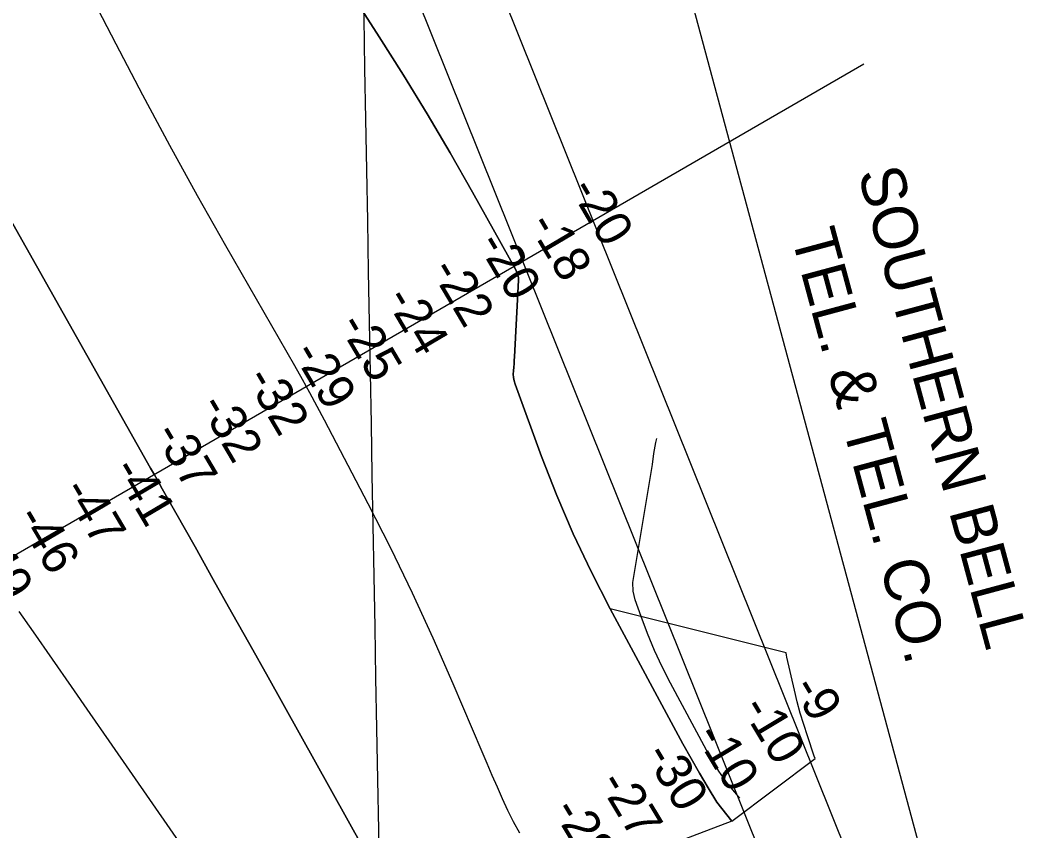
# Model space of a CAD drawing. Extents: x 3914892 to 3953151, y 242587 to 268572.
# Drawn here: x 3939590 to 3941476, y 257865 to 259377 of the extents above; entities that cross this region are included whole.
import ezdxf

# ---------------------------------------------------------------- set-up
doc = ezdxf.new("R2010")
doc.units = 0
for name, color, linetype in [('V-GRID-MAJR', 7, 'Continuous'), ('V-RIVR-RANG', 7, 'Continuous'), ('V-TOPO-DPTH', 7, 'Continuous'), ('V-TOPO-MAJR', 7, 'Continuous'), ('V-TOPO-MINR', 7, 'Continuous'), ('V-UTIL-IDEN', 7, 'Continuous'), ('V-UTIL-LINE', 7, 'Continuous')]:
    doc.layers.add(name, color=color, linetype=linetype)

msp = doc.modelspace()

# ---------------------------------------------------------------- linework, layer by layer
at = {"layer": 'V-GRID-MAJR'}
msp.add_spline([(3940428.975, 248401.018), (3940319.725, 254457.832), (3940210.42, 260517.73), (3940101.115, 266577.62), (3940101.059, 266580.712)], degree=3, dxfattribs=at)
at = {"layer": 'V-TOPO-DPTH'}
msp.add_line((3940916.7946737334, 257883.60607081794), (3940592.1881537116, 257760.18646806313), dxfattribs=at)
for points in [[(3940045.042517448, 259679.64535009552), (3940259.416958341, 259346.02710651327), (3940304.4262905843, 259274.52676481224), (3940348.5364647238, 259202.48730646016), (3940391.297901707, 259129.63917313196), (3940433.1601805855, 259056.25192315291), (3940513.3725932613, 258912.54215419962), (3940515.295097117, 258908.56889559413), (3940516.0658002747, 258906.50344468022), (3940516.741229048, 258904.39858296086), (3940518.725091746, 258897.37706114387), (3940518.887253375, 258896.70905295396), (3940519.1494097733, 258893.289819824), (3940519.103615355, 258891.91121463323), (3940511.435853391, 258748.9816995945), (3940511.044543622, 258742.54425098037), (3940510.5922374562, 258736.11152761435), (3940510.0484366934, 258729.68589212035), (3940509.4436395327, 258723.26498187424), (3940509.236969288, 258716.9035478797), (3940509.597414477, 258710.61357017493), (3940510.808532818, 258704.4307769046), (3940512.5867665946, 258698.31943992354), (3940562.0141765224, 258563.6274434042), (3940590.4767664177, 258490.91323125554), (3940620.966441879, 258419.11141004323), (3940654.4967456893, 258348.67817523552), (3940690.0541350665, 258279.15733136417), (3940825.535124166, 258027.68460056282), (3940840.7424244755, 258000.0505592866), (3940856.274320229, 257972.6040456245), (3940872.293109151, 257945.43882338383), (3940888.6364935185, 257918.46112875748), (3940916.7946737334, 257883.60607081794)], [(3940521.2747341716, 257861.190364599), (3940509.655623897, 257881.96401162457), (3940499.0032929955, 257903.2495931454), (3940488.9954816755, 257924.87646432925), (3940479.501421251, 257946.7725954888), (3940470.044684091, 257968.68477791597), (3940460.643931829, 257990.62103724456), (3940451.2805028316, 258012.57334784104), (3940397.336112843, 258139.4933336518), (3940360.0272818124, 258224.44432548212), (3940321.3852736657, 258308.76501382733), (3940280.743499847, 258392.1402469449), (3940238.7685489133, 258474.88517657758), (3940157.15210671, 258631.12796396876), (3940143.6413121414, 258656.62519658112), (3940129.9317093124, 258682.0135558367), (3940115.923894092, 258707.23860505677), (3940101.7172706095, 258732.3547809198), (3939973.24557912, 258956.39167766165), (3939920.6512738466, 259049.5280964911), (3939868.8835262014, 259143.11463003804), (3939818.355614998, 259237.3763356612), (3939768.654261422, 259332.08815600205), (3939692.0899913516, 259480.36083535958)], [(3940521.2747341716, 257861.190364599), (3940509.655623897, 257881.96401162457), (3940499.0032929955, 257903.2495931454), (3940488.9954816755, 257924.87646432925), (3940479.501421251, 257946.7725954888), (3940470.044684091, 257968.68477791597), (3940460.643931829, 257990.62103724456), (3940451.2805028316, 258012.57334784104), (3940397.336112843, 258139.4933336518), (3940360.0272818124, 258224.44432548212), (3940321.3852736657, 258308.76501382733), (3940280.743499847, 258392.1402469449), (3940238.7685489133, 258474.88517657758), (3940157.15210671, 258631.12796396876), (3940143.6413121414, 258656.62519658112), (3940129.9317093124, 258682.0135558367), (3940115.923894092, 258707.23860505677), (3940101.7172706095, 258732.3547809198), (3939973.24557912, 258956.39167766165), (3939920.6512738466, 259049.5280964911), (3939868.8835262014, 259143.11463003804), (3939818.355614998, 259237.3763356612), (3939768.654261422, 259332.08815600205), (3939692.0899913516, 259480.36083535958)], [(3939481.8310250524, 259163.69193205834), (3939832.9714719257, 258541.88976801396), (3939840.2523454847, 258528.98952955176), (3939847.5290996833, 258516.08696916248), (3939854.7996748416, 258503.18092588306), (3939862.0661306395, 258490.27256067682), (3939915.828914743, 258394.71311202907), (3939949.938412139, 258334.00353257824), (3939984.0008951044, 258273.26762191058), (3940017.992856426, 258212.49221441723), (3940051.937803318, 258151.6904757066), (3940316.8800802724, 257676.48161290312)], [(3940316.8800802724, 257676.48161290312), (3940051.937803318, 258151.6904757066), (3940017.992856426, 258212.49221441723), (3939984.0008951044, 258273.26762191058), (3939949.938412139, 258334.00353257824), (3939915.828914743, 258394.71311202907), (3939862.0661306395, 258490.27256067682), (3939854.7996748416, 258503.18092588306), (3939847.5290996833, 258516.08696916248), (3939840.2523454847, 258528.98952955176), (3939832.9714719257, 258541.88976801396), (3939481.8310250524, 259163.69193205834)], [(3940916.7946737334, 257883.60607081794), (3941071.9874333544, 258000.2995589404), (3941070.4826231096, 258004.7867699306), (3941057.63869986, 258042.28013250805), (3941050.7773749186, 258063.36526431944), (3941044.3543190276, 258084.57576696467), (3941038.588666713, 258105.9743258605), (3941033.261283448, 258127.49825558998), (3941019.018173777, 258189.10541415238), (3941018.3900835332, 258193.0934200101), (3941018.136960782, 258197.078780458), (3940690.0541350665, 258279.15733136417)], [(3940690.0541350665, 258279.15733136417), (3940825.535124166, 258027.68460056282), (3940840.7424244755, 258000.0505592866), (3940856.274320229, 257972.6040456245), (3940872.293109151, 257945.43882338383), (3940888.6364935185, 257918.46112875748), (3940916.7946737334, 257883.60607081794)]]:
    msp.add_lwpolyline(points, dxfattribs=at)
at = {"layer": 'V-TOPO-MAJR'}
msp.add_lwpolyline([(3940070.0098628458, 257579.46278085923), (3939755.701372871, 258033.1211966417), (3939720.4785539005, 258083.90690546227), (3939685.2225123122, 258134.6695160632), (3939649.9166367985, 258185.3974793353), (3939614.577538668, 258236.10234438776), (3939588.0782612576, 258274.08398232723)], dxfattribs=at)
at = {"layer": 'V-TOPO-MINR'}
for points in [[(3940916.7946737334, 257883.60607081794), (3940888.6364935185, 257918.46112875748), (3940872.293109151, 257945.43882338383), (3940856.274320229, 257972.6040456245), (3940840.7424244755, 258000.0505592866), (3940825.535124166, 258027.68460056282), (3940690.0541350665, 258279.15733136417), (3940654.4967456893, 258348.67817523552), (3940620.966441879, 258419.11141004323), (3940590.4767664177, 258490.91323125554), (3940562.0141765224, 258563.6274434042), (3940512.5867665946, 258698.31943992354), (3940510.808532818, 258704.4307769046), (3940509.597414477, 258710.61357017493), (3940509.236969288, 258716.9035478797), (3940509.4436395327, 258723.26498187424), (3940510.0484366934, 258729.68589212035), (3940510.5922374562, 258736.11152761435), (3940511.044543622, 258742.54425098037), (3940511.435853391, 258748.9816995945), (3940519.103615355, 258891.91121463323), (3940519.1494097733, 258893.289819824), (3940518.887253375, 258896.70905295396), (3940518.725091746, 258897.37706114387), (3940516.741229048, 258904.39858296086), (3940516.0658002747, 258906.50344468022), (3940515.295097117, 258908.56889559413), (3940513.3725932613, 258912.54215419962), (3940433.1601805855, 259056.25192315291), (3940391.297901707, 259129.63917313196), (3940348.5364647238, 259202.48730646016), (3940304.4262905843, 259274.52676481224), (3940259.416958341, 259346.02710651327), (3940045.042517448, 259679.64535009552)], [(3940521.2747341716, 257861.190364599), (3940509.655623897, 257881.96401162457), (3940499.0032929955, 257903.2495931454), (3940488.9954816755, 257924.87646432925), (3940479.501421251, 257946.7725954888), (3940470.044684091, 257968.68477791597), (3940460.643931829, 257990.62103724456), (3940451.2805028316, 258012.57334784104), (3940397.336112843, 258139.4933336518), (3940360.0272818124, 258224.44432548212), (3940321.3852736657, 258308.76501382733), (3940280.743499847, 258392.1402469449), (3940238.7685489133, 258474.88517657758), (3940157.15210671, 258631.12796396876), (3940143.6413121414, 258656.62519658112), (3940129.9317093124, 258682.0135558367), (3940115.923894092, 258707.23860505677), (3940101.7172706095, 258732.3547809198), (3939973.24557912, 258956.39167766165), (3939920.6512738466, 259049.5280964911), (3939868.8835262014, 259143.11463003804), (3939818.355614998, 259237.3763356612), (3939768.654261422, 259332.08815600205), (3939692.0899913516, 259480.36083535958)], [(3940316.8800802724, 257676.48161290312), (3940051.937803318, 258151.6904757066), (3940017.992856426, 258212.49221441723), (3939984.0008951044, 258273.26762191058), (3939949.938412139, 258334.00353257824), (3939915.828914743, 258394.71311202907), (3939862.0661306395, 258490.27256067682), (3939854.7996748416, 258503.18092588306), (3939847.5290996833, 258516.08696916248), (3939840.2523454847, 258528.98952955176), (3939832.9714719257, 258541.88976801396), (3939481.8310250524, 259163.69193205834)], [(3940931.7621347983, 257926.34766184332), (3940922.088612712, 257937.50243969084), (3940908.4096784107, 257953.3660199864), (3940900.8666048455, 257964.33974285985), (3940892.5693273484, 257976.8401308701), (3940884.5486042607, 257989.50938576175), (3940876.942712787, 258002.4319409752), (3940869.613375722, 258015.52336307), (3940802.072049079, 258140.88985305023), (3940786.695478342, 258171.13178190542), (3940772.3011314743, 258201.80646002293), (3940759.380120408, 258233.13026203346), (3940747.441333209, 258264.88681330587), (3940736.4781410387, 258296.2961578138), (3940733.0126962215, 258312.51668829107), (3940732.163604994, 258328.5540451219), (3940768.8571837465, 258548.72593687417), (3940771.505786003, 258569.20815368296), (3940775.1159646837, 258589.60018195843), (3940776.6397154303, 258596.73632916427)], [(3941071.9874333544, 258000.2995589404), (3941070.4826231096, 258004.7867699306), (3941057.63869986, 258042.28013250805), (3941050.7773749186, 258063.36526431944), (3941044.3543190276, 258084.57576696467), (3941038.588666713, 258105.9743258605), (3941033.261283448, 258127.49825558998), (3941019.018173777, 258189.10541415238), (3941018.3900835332, 258193.0934200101), (3941018.136960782, 258197.078780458)]]:
    msp.add_lwpolyline(points, dxfattribs=at)
at = {"layer": 'V-UTIL-LINE'}
for p, q in [((3941072.986, 257567.442), (3939526.299, 261421.028)), ((3941262.278, 257498.559), (3939715.592, 261352.14800000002)), ((3941339.742, 257565.166), (3940398.835, 261058.278))]:
    msp.add_line(p, q, dxfattribs=at)
msp.add_lwpolyline([(3941163.0146340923, 259295.05838473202), (3936055.712848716, 256340.1292946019)], dxfattribs=at)

# ---------------------------------------------------------------- texts
at = {"layer": 'V-RIVR-RANG'}
for s, height, rotation, p in [('-20', 67.0000000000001, 300.30832571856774, (3940613.6761542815, 259061.91486141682)), ('-18', 67.00000000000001, 300.58983333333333, (3940535.927216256, 258996.13250640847)), ('-20', 67.00000000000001, 300.58983333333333, (3940440.99297931, 258960.2160530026)), ('-22', 67.00000000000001, 300.58983333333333, (3940353.8453384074, 258911.12954263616)), ('-24', 67.00000000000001, 300.58983333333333, (3940269.112916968, 258857.9557732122)), ('-25', 67.00000000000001, 300.58983333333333, (3940181.964276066, 258808.86926284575)), ('-29', 67.00000000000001, 300.58983333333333, (3940096.6949169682, 258756.6037732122)), ('-32', 67.00000000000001, 300.58983333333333, (3940008.7418695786, 258708.87968253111)), ('-32', 67.00000000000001, 300.58983333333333, (3939922.5328695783, 258658.20468253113)), ('-37', 67.00000000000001, 300.58983333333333, (3939837.5259688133, 258605.49522031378)), ('-41', 67.00000000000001, 300.58983333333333, (3939760.4509195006, 258539.36829656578)), ('-47', 67.00000000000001, 300.58983333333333, (3939666.9882506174, 258500.96424104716)), ('-46', 67.00000000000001, 300.58983333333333, (3939580.919495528, 258450.05100378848)), ('-49', 67.00000000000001, 300.58983333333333, (3939494.8447299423, 258399.14793384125)), ('-9', 67.00000000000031, 300.6983257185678, (3941027.506918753, 258132.0953111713)), ('-10', 67, 300.981, (3940933.1043599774, 258094.58750750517)), ('-10', 67, 300.981, (3940847.243359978, 258043.32350750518)), ('-30', 67, 300.981, (3940752.421780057, 258006.98629034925)), ('-27', 67, 300.981, (3940667.0978263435, 257954.8288234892)), ('-28', 67, 300.981, (3940581.1071245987, 257903.78084567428))]:
    msp.add_text(s, height=height, rotation=rotation, dxfattribs=at).set_placement(p)
at = {"layer": 'V-UTIL-IDEN'}
for s, height, rotation, p in [('1-16" GAS PIPELINE', 82.99983200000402, 288.90900813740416, (3941401.208545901, 260018.03314976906)), ('SOUTHERN BELL', 82.999832, 285.06765435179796, (3941151.2975300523, 259092.3858270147)), ('TEL. & TEL. CO.', 82.999832, 285.06765435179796, (3941026.796527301, 258975.92937861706))]:
    msp.add_text(s, height=height, rotation=rotation, dxfattribs=at).set_placement(p)

doc.saveas('drawing.dxf')
